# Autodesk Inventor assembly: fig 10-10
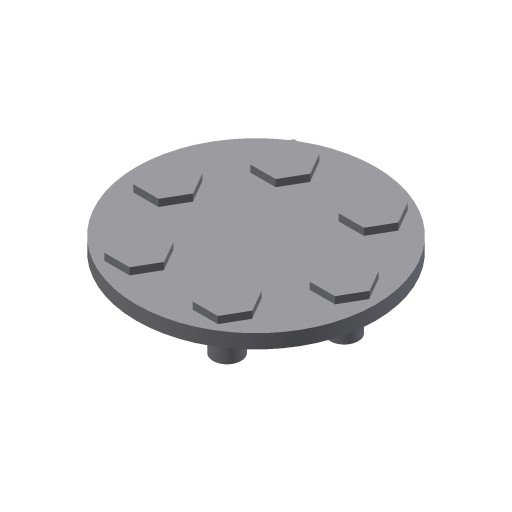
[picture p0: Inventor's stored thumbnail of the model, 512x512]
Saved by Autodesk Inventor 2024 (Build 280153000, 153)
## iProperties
Created: 2008-05
Part Number: fig 10-10
Document SubType Name: Assembly
Designer: CADCIM
Author: CADCIM
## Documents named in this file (3)
- D:\PROJECTS\Project 2023\RESOURCES INVENTOR 2024\RESOURCES INVENTOR 2024\Inventor_2023_Part\Inventor_2024_Part\c10_Inv_2024_prt\fig 10-10.iam
- D:\PROJECTS\Project 2023\RESOURCES INVENTOR 2024\RESOURCES INVENTOR 2024\Inventor_2023_Part\Inventor_2024_Part\c10_Inv_2024_prt\Part4.ipt
- D:\PROJECTS\Project 2023\RESOURCES INVENTOR 2024\RESOURCES INVENTOR 2024\Inventor_2023_Part\Inventor_2024_Part\c10_Inv_2024_prt\Part5.ipt
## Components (7 placed, 2 different names)
1. Part4:1
2. Part5:1
3. Part5:2
4. Part5:3
5. Part5:4
6. Part5:5
7. Part5:6
